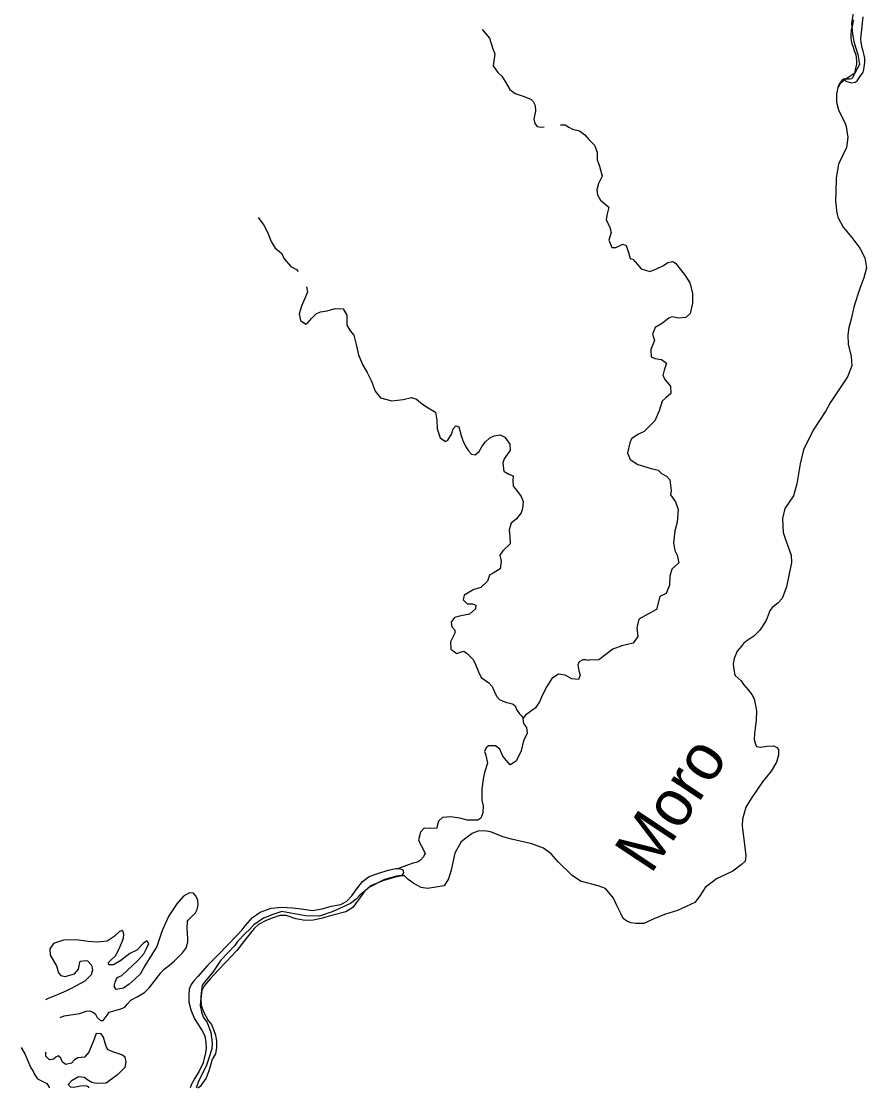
# Model space of a CAD drawing. Extents: x -492261 to -432772, y 1441225 to 1452922.
# Drawn here: x -459430.8 to -459334.4, y 1451554.7 to 1451676.4 of the extents above; entities that cross this region are included whole.
import ezdxf

# ---------------------------------------------------------------- set-up
doc = ezdxf.new("R2010")
doc.units = 0
doc.layers.add('Default', color=7, linetype='Continuous')

msp = doc.modelspace()

# ---------------------------------------------------------------- linework, layer by layer
at = {"layer": 'Default'}
for points in [[(-459335.93, 1451677.35), (-459336.12, 1451676.24), (-459336.01, 1451674.97), (-459335.8, 1451673.97), (-459335.38, 1451672.63), (-459335.2, 1451671.51), (-459335.74, 1451670.52), (-459336.4, 1451670.07), (-459336.92, 1451669.75), (-459337.45, 1451669.28), (-459337.66, 1451668.88), (-459337.81, 1451668.12), (-459337.81, 1451667.22), (-459337.58, 1451666.32), (-459337.29, 1451665.68), (-459336.87, 1451664.89), (-459336.7, 1451664.42), (-459336.51, 1451663.17), (-459336.68, 1451662.02), (-459337.59, 1451660.13), (-459337.87, 1451658.57), (-459337.89, 1451656.89), (-459337.93, 1451655.96), (-459337.86, 1451655.31), (-459337.8, 1451654.76), (-459337.65, 1451654.09), (-459337.04, 1451652.93), (-459336.06, 1451651.76), (-459335.17, 1451650.56), (-459334.58, 1451649.43), (-459334.38, 1451648.31), (-459334.69, 1451647.15), (-459335.15, 1451645.93), (-459335.79, 1451643.98), (-459336.16, 1451642.44), (-459336.41, 1451641.48), (-459336.53, 1451640.65), (-459336.47, 1451639.59), (-459336.16, 1451638.18), (-459336.07, 1451637.13), (-459336.58, 1451635.88), (-459337.49, 1451634.48), (-459338.54, 1451632.89), (-459339.03, 1451631.99), (-459340.46, 1451629.79), (-459341.57, 1451627.55), (-459341.97, 1451625.94), (-459342.34, 1451623.64), (-459342.73, 1451622.28), (-459343.73, 1451620.82), (-459343.99, 1451619.68), (-459343.92, 1451618.11), (-459343.7, 1451617.54), (-459343.32, 1451616.45), (-459342.99, 1451615.53), (-459342.94, 1451614.68), (-459343.52, 1451611.9), (-459344.01, 1451610.58), (-459344.51, 1451610.02), (-459345.17, 1451609.52), (-459345.41, 1451609.14)], [(-459335.87, 1451676.61), (-459335.95, 1451676.3), (-459336.04, 1451675.82), (-459336.13, 1451675.47), (-459336.2, 1451674.85), (-459336.2, 1451674.54), (-459336.14, 1451674.23), (-459336.06, 1451673.87), (-459335.97, 1451673.61), (-459335.79, 1451673.12), (-459335.61, 1451672.62), (-459335.57, 1451672.3), (-459335.54, 1451671.84), (-459335.55, 1451671.55), (-459335.69, 1451670.91), (-459335.78, 1451670.44), (-459335.9, 1451670.15), (-459335.97, 1451670.02), (-459336.09, 1451669.89), (-459336.29, 1451669.85), (-459336.56, 1451669.83), (-459336.85, 1451669.84), (-459337.02, 1451669.83), (-459336.92, 1451669.74), (-459336.78, 1451669.63), (-459336.62, 1451669.56), (-459336.39, 1451669.49), (-459336.14, 1451669.43), (-459335.9, 1451669.45), (-459335.68, 1451669.49), (-459335.46, 1451669.64), (-459335.3, 1451669.88), (-459335.15, 1451670.09), (-459334.79, 1451670.63), (-459334.71, 1451670.93), (-459334.58, 1451671.75), (-459334.59, 1451672.19), (-459334.66, 1451672.59), (-459334.77, 1451673.03), (-459334.9, 1451673.42), (-459335.02, 1451674.05), (-459335.05, 1451674.44), (-459335, 1451674.88), (-459334.93, 1451675.45), (-459334.85, 1451676.28), (-459334.77, 1451676.95)], [(-459378.23, 1451675.51), (-459377.4, 1451674.51), (-459377.08, 1451673.41), (-459376.78, 1451672.72)], [(-459376.78, 1451672.72), (-459376.98, 1451671.34), (-459376.47, 1451670.58), (-459376, 1451670.17), (-459375.61, 1451669.55), (-459375.1, 1451668.66), (-459374.46, 1451668.2), (-459373.55, 1451667.91), (-459372.68, 1451667.55), (-459372.41, 1451667.3), (-459372.2, 1451666.82), (-459372.17, 1451666.18), (-459372.33, 1451665.32), (-459372.22, 1451664.78), (-459371.97, 1451664.43), (-459371.56, 1451664.35), (-459371.18, 1451664.39)], [(-459337.02, 1451669.83), (-459337.22, 1451669.67), (-459337.35, 1451669.49), (-459337.5, 1451669.25), (-459337.66, 1451668.88), (-459337.81, 1451668.12), (-459337.81, 1451667.22), (-459337.58, 1451666.32), (-459337.29, 1451665.68), (-459336.87, 1451664.89), (-459336.7, 1451664.42), (-459336.51, 1451663.17), (-459336.68, 1451662.02), (-459337.59, 1451660.13), (-459337.87, 1451658.57), (-459337.89, 1451656.89), (-459337.93, 1451655.96), (-459337.86, 1451655.31), (-459337.8, 1451654.76), (-459337.65, 1451654.09), (-459337.04, 1451652.93), (-459336.06, 1451651.76), (-459335.17, 1451650.56), (-459334.58, 1451649.43), (-459334.38, 1451648.31), (-459334.69, 1451647.15), (-459335.15, 1451645.93), (-459335.79, 1451643.98), (-459336.16, 1451642.44), (-459336.41, 1451641.48), (-459336.53, 1451640.65), (-459336.47, 1451639.59), (-459336.16, 1451638.18), (-459336.07, 1451637.13), (-459336.58, 1451635.88), (-459337.49, 1451634.48), (-459338.54, 1451632.89), (-459339.03, 1451631.99), (-459340.46, 1451629.79), (-459341.57, 1451627.55), (-459341.97, 1451625.94), (-459342.34, 1451623.64), (-459342.73, 1451622.28), (-459343.73, 1451620.82), (-459343.99, 1451619.68), (-459343.92, 1451618.11), (-459343.7, 1451617.54), (-459343.32, 1451616.45), (-459342.99, 1451615.53), (-459342.94, 1451614.68), (-459343.52, 1451611.9), (-459344.01, 1451610.58), (-459344.51, 1451610.02), (-459345.17, 1451609.52), (-459345.41, 1451609.14)], [(-459369.32, 1451664.63), (-459368.76, 1451664.61), (-459368.35, 1451664.35), (-459367.94, 1451664.14), (-459367.13, 1451663.95), (-459366.53, 1451663.49), (-459366.05, 1451662.9), (-459365.44, 1451662.32), (-459365.14, 1451661.49), (-459365.12, 1451660.62), (-459364.87, 1451659.89), (-459364.54, 1451658.77), (-459364.97, 1451657.94), (-459365.17, 1451657.21), (-459365.1, 1451656.62), (-459364.75, 1451656.03), (-459363.81, 1451655.24), (-459363.97, 1451654.47), (-459364.1, 1451653.8), (-459363.68, 1451652.92), (-459363.52, 1451652.35), (-459363.78, 1451651.46), (-459363.45, 1451650.61), (-459363.01, 1451650.61), (-459362.2, 1451650.99), (-459361.81, 1451650.84), (-459361.56, 1451650.07), (-459361.34, 1451649.38), (-459361.05, 1451649.29), (-459360.53, 1451648.7), (-459360.09, 1451648.17), (-459359.11, 1451647.9), (-459358.37, 1451648.18), (-459357.55, 1451648.58), (-459357.05, 1451648.9), (-459356.49, 1451649.03), (-459356.19, 1451648.83), (-459355.63, 1451648.13), (-459355.1, 1451647.44), (-459354.54, 1451646.58), (-459354.24, 1451645.43), (-459354.23, 1451644.26), (-459354.5, 1451643.09), (-459354.99, 1451642.64), (-459355.8, 1451642.55), (-459356.55, 1451642.72), (-459356.93, 1451642.55), (-459357.68, 1451641.98), (-459358.5, 1451641.48), (-459358.82, 1451640.74), (-459358.57, 1451640.01), (-459358.99, 1451638.99), (-459358.96, 1451638.15), (-459358.56, 1451637.95), (-459357.78, 1451637.85), (-459357.2, 1451637.41), (-459357.49, 1451636.61), (-459357.64, 1451636), (-459357.37, 1451635.53), (-459356.74, 1451634.78), (-459356.73, 1451633.96), (-459357.29, 1451633.48), (-459357.7, 1451633.09), (-459358.04, 1451631.99), (-459358.53, 1451630.83), (-459359.76, 1451629.61), (-459360.48, 1451629.3), (-459361.22, 1451628.8), (-459361.38, 1451628.33), (-459361.67, 1451627.19), (-459361.35, 1451626.43), (-459360.5, 1451625.84), (-459358.95, 1451625.42), (-459358.18, 1451625.2), (-459357.77, 1451624.84), (-459357.21, 1451624.53), (-459356.82, 1451624.09), (-459356.69, 1451622.89), (-459356.77, 1451622.39), (-459356.17, 1451621.6), (-459355.87, 1451620.74), (-459356, 1451619.26), (-459356.25, 1451618.28), (-459356.42, 1451616.92)], [(-459403.79, 1451654.06), (-459403.16, 1451653.19), (-459402.91, 1451652.74), (-459402.64, 1451652.18), (-459402.31, 1451651.3), (-459401.86, 1451650.55), (-459401.19, 1451650.01), (-459400.8, 1451649.31), (-459400.07, 1451648.47), (-459399.42, 1451648.11), (-459399.24, 1451647.88)], [(-459398.3, 1451646.13), (-459398.17, 1451645.53), (-459398.85, 1451643.91), (-459399.11, 1451643.04), (-459398.96, 1451642.28), (-459398.37, 1451641.88), (-459398.19, 1451641.95), (-459397.66, 1451642.54), (-459397.19, 1451643.05), (-459396.67, 1451643.27), (-459395.93, 1451643.38), (-459395.02, 1451643.66), (-459394.11, 1451643.62), (-459393.7, 1451642.89), (-459393.67, 1451641.76), (-459393.29, 1451641.12), (-459392.89, 1451640.62), (-459392.61, 1451639.56), (-459392.34, 1451638.36), (-459391.89, 1451637.26), (-459391.35, 1451636.35), (-459390.85, 1451635.35), (-459390.45, 1451634.24), (-459389.86, 1451633.48), (-459388.53, 1451633.11), (-459387.26, 1451633.28), (-459386.3, 1451633.49), (-459385.74, 1451633.33), (-459385.04, 1451632.73), (-459384.39, 1451632.34), (-459383.56, 1451631.82), (-459383.42, 1451630.91), (-459383.36, 1451629.92), (-459383.03, 1451628.91), (-459382.41, 1451628.5), (-459382.15, 1451628.65), (-459381.76, 1451629.33), (-459381.56, 1451629.92), (-459381.26, 1451630.28), (-459380.89, 1451630.14), (-459380.64, 1451629.17), (-459380.44, 1451628.6), (-459380.09, 1451627.89), (-459379.8, 1451627.42), (-459379.45, 1451627.05), (-459379.06, 1451626.96), (-459378.57, 1451627.36), (-459378.23, 1451627.96), (-459377.88, 1451628.44), (-459377.37, 1451628.91), (-459376.88, 1451629.14), (-459376.2, 1451629.25), (-459375.65, 1451628.97), (-459375.09, 1451628.17), (-459375.04, 1451627.49), (-459375.46, 1451626.87), (-459375.72, 1451626.51), (-459375.9, 1451626.06), (-459375.78, 1451625.07), (-459375.65, 1451625.02), (-459375.21, 1451624.77), (-459374.72, 1451624.58), (-459374.76, 1451624.03), (-459374.71, 1451623.37), (-459374.33, 1451622.94), (-459373.8, 1451622.21), (-459373.58, 1451621.65), (-459373.63, 1451620.85), (-459373.81, 1451620.36), (-459374.31, 1451619.67), (-459374.94, 1451619.16), (-459375.17, 1451618.4), (-459375.07, 1451617.59), (-459375.05, 1451616.8), (-459375.9, 1451616.02), (-459376.24, 1451615.53), (-459376.07, 1451614.78), (-459376.19, 1451613.96), (-459376.98, 1451613.46), (-459377.4, 1451613.22), (-459377.63, 1451612.55), (-459378.38, 1451611.84), (-459379.19, 1451611.6), (-459380.28, 1451610.96), (-459380.41, 1451610.42), (-459379.94, 1451609.97), (-459379.34, 1451609.96), (-459378.96, 1451609.79)], [(-459356.42, 1451616.92), (-459356.26, 1451616.05), (-459356.01, 1451615.51), (-459355.82, 1451614.64), (-459356.61, 1451613.92), (-459356.82, 1451613.1), (-459356.87, 1451612.07), (-459357.25, 1451611.13), (-459357.99, 1451610.81), (-459358.36, 1451609.3), (-459359.28, 1451608.81), (-459360.37, 1451608.22), (-459360.6, 1451607.23), (-459360.49, 1451606.24), (-459361, 1451605.46), (-459362.29, 1451605.17), (-459363.32, 1451604.78), (-459363.99, 1451604.28), (-459364.94, 1451603.57), (-459366.11, 1451603.53), (-459366.11, 1451603.5), (-459366.41, 1451603.57), (-459366.75, 1451603.57), (-459367.16, 1451603.34), (-459367.34, 1451602.98), (-459367.2, 1451602.31), (-459367.06, 1451601.81), (-459367.26, 1451601.34), (-459368, 1451601.39), (-459368.77, 1451601.82), (-459369.55, 1451601.92), (-459370.31, 1451601.45), (-459370.85, 1451600.54), (-459371.35, 1451599.59), (-459371.69, 1451598.76), (-459372.17, 1451598.1), (-459372.73, 1451597.66), (-459373.28, 1451597.27), (-459373.6, 1451596.86), (-459373.51, 1451596.3), (-459373.17, 1451595.86), (-459373.11, 1451595.19), (-459373.51, 1451594.33), (-459373.81, 1451593.17), (-459374.38, 1451592), (-459375.06, 1451591.58), (-459375.87, 1451592.56), (-459376.23, 1451593.37), (-459376.71, 1451593.77), (-459377.53, 1451593.74), (-459377.8, 1451593.53), (-459377.96, 1451593.1), (-459377.81, 1451592.67), (-459377.65, 1451591.77), (-459377.98, 1451590.69), (-459378.14, 1451589.96), (-459378.29, 1451588.84), (-459378.28, 1451587.54), (-459378.13, 1451586.91), (-459378.17, 1451586.1), (-459378.4, 1451585.51), (-459378.74, 1451585.25), (-459379.94, 1451585.26), (-459380.79, 1451585.48), (-459381.84, 1451585.65), (-459382.76, 1451585.58), (-459383.22, 1451585.14), (-459383.33, 1451584.78), (-459383.42, 1451584.36), (-459384.13, 1451584.3), (-459384.87, 1451584.34), (-459385.26, 1451583.89), (-459385.51, 1451583.03), (-459385.33, 1451582.58), (-459385.01, 1451582.05), (-459384.76, 1451581.47), (-459384.83, 1451581.34), (-459384.94, 1451581.08), (-459385.29, 1451580.7), (-459385.63, 1451580.49), (-459386.12, 1451580.36), (-459386.77, 1451580.12), (-459387.28, 1451579.94), (-459387.58, 1451579.82), (-459387.73, 1451579.75)], [(-459345.41, 1451609.14), (-459345.62, 1451608.68), (-459345.85, 1451608.07), (-459346.57, 1451606.94), (-459347.24, 1451606.27), (-459348.17, 1451605.66), (-459348.44, 1451605.43), (-459348.66, 1451605.12), (-459349.16, 1451604.55), (-459349.49, 1451603.72), (-459349.59, 1451603.11), (-459349.58, 1451602.74), (-459349.46, 1451601.99), (-459349.38, 1451601.77), (-459348.71, 1451601.16), (-459348.42, 1451600.74), (-459347.9, 1451600.13), (-459347.46, 1451599.6), (-459347.2, 1451599.13), (-459347.05, 1451598.36), (-459346.95, 1451597.73), (-459346.97, 1451596.73), (-459347.09, 1451595.75), (-459347.17, 1451595.15), (-459347.22, 1451594.47), (-459347.11, 1451594.07), (-459346.95, 1451593.68), (-459346.5, 1451593.61), (-459345.78, 1451593.71), (-459345, 1451593.74), (-459344.9, 1451593.72), (-459344.62, 1451593.55), (-459344.44, 1451593.33), (-459344.42, 1451592.7), (-459344.65, 1451591.9), (-459345.26, 1451590.85), (-459346.25, 1451589.66), (-459347.54, 1451587.74), (-459348.16, 1451586.75), (-459348.54, 1451585.4), (-459348.59, 1451584.63), (-459348.46, 1451583.68), (-459348.3, 1451582.48), (-459348.16, 1451581.18), (-459348.24, 1451580.58), (-459348.7, 1451580.16), (-459349.63, 1451579.43), (-459351.5, 1451578.59), (-459352.79, 1451577.57), (-459353.39, 1451576.68), (-459353.98, 1451575.88), (-459355.95, 1451574.97), (-459357.44, 1451574.49), (-459358.74, 1451573.97), (-459359.8, 1451573.49), (-459360.3, 1451573.47), (-459360.7, 1451573.46), (-459361.3, 1451573.54), (-459361.73, 1451573.73), (-459362.14, 1451574.04), (-459362.41, 1451574.63), (-459362.89, 1451575.52), (-459363.26, 1451576.38), (-459364.17, 1451577.48), (-459365, 1451577.76), (-459367.04, 1451578.32), (-459367.96, 1451578.96), (-459369.56, 1451580.52), (-459370.36, 1451581.44), (-459371.23, 1451582.09), (-459372.59, 1451582.55), (-459374.91, 1451583.1), (-459375.89, 1451583.37), (-459376.4, 1451583.58), (-459377.28, 1451583.93), (-459377.98, 1451584.05), (-459378.73, 1451584.03), (-459379.4, 1451583.73), (-459380.1, 1451583.21), (-459380.64, 1451582.79), (-459381.37, 1451581.49), (-459381.55, 1451580.61), (-459381.79, 1451579.55), (-459382.08, 1451578.58), (-459382.56, 1451577.79), (-459384.47, 1451577.46), (-459385.22, 1451577.58), (-459386.03, 1451578.06), (-459386.7, 1451578.49), (-459387.11, 1451578.9), (-459387.54, 1451578.94), (-459388.01, 1451578.87), (-459389.37, 1451578.48), (-459391.11, 1451577.62), (-459392.21, 1451576.7), (-459392.6, 1451576.27), (-459393.25, 1451575.77), (-459395.35, 1451574.8), (-459396.8, 1451574.3), (-459398.4, 1451574.37), (-459400.08, 1451574.65)], [(-459345.41, 1451609.14), (-459345.62, 1451608.68), (-459345.85, 1451608.07), (-459346.57, 1451606.94), (-459347.24, 1451606.27), (-459348.17, 1451605.66), (-459348.44, 1451605.43), (-459348.66, 1451605.12), (-459349.16, 1451604.55), (-459349.49, 1451603.72), (-459349.59, 1451603.11), (-459349.58, 1451602.74), (-459349.46, 1451601.99), (-459349.38, 1451601.77), (-459348.71, 1451601.16), (-459348.42, 1451600.74), (-459347.9, 1451600.13), (-459347.46, 1451599.6), (-459347.2, 1451599.13), (-459347.05, 1451598.36), (-459346.95, 1451597.73), (-459346.97, 1451596.73), (-459347.09, 1451595.75), (-459347.17, 1451595.15), (-459347.22, 1451594.47), (-459347.11, 1451594.07), (-459346.95, 1451593.68), (-459346.5, 1451593.61), (-459345.78, 1451593.71), (-459345, 1451593.74), (-459344.9, 1451593.72), (-459344.62, 1451593.55), (-459344.44, 1451593.33), (-459344.42, 1451592.7), (-459344.65, 1451591.9), (-459345.26, 1451590.85), (-459346.25, 1451589.66), (-459347.54, 1451587.74), (-459348.16, 1451586.75), (-459348.54, 1451585.4), (-459348.59, 1451584.63), (-459348.46, 1451583.68), (-459348.3, 1451582.48), (-459348.16, 1451581.18), (-459348.24, 1451580.58), (-459348.7, 1451580.16), (-459349.63, 1451579.43), (-459351.5, 1451578.59), (-459352.79, 1451577.57), (-459353.39, 1451576.68), (-459353.98, 1451575.88), (-459355.95, 1451574.97), (-459357.44, 1451574.49), (-459358.74, 1451573.97), (-459359.8, 1451573.49), (-459360.3, 1451573.47), (-459360.7, 1451573.46), (-459361.3, 1451573.54), (-459361.73, 1451573.73), (-459362.14, 1451574.04), (-459362.41, 1451574.63), (-459362.89, 1451575.52), (-459363.26, 1451576.38), (-459364.17, 1451577.48), (-459365, 1451577.76), (-459367.04, 1451578.32), (-459367.96, 1451578.96), (-459369.56, 1451580.52), (-459370.36, 1451581.44), (-459371.23, 1451582.09), (-459372.59, 1451582.55), (-459374.91, 1451583.1), (-459375.89, 1451583.37), (-459376.4, 1451583.58), (-459377.28, 1451583.93), (-459377.98, 1451584.05), (-459378.73, 1451584.03), (-459379.4, 1451583.73), (-459380.1, 1451583.21), (-459380.64, 1451582.79), (-459381.37, 1451581.49), (-459381.55, 1451580.61), (-459381.79, 1451579.55), (-459382.08, 1451578.58), (-459382.56, 1451577.79), (-459384.47, 1451577.46), (-459385.22, 1451577.58), (-459386.03, 1451578.06), (-459386.7, 1451578.49), (-459387.11, 1451578.9), (-459387.45, 1451578.93)], [(-459378.96, 1451609.79), (-459379.02, 1451609.4), (-459379.67, 1451608.79), (-459380.84, 1451608.54), (-459381.41, 1451608.41), (-459381.79, 1451607.87), (-459381.69, 1451607.33), (-459381.37, 1451606.97), (-459381.38, 1451606.6), (-459381.84, 1451605.62), (-459381.82, 1451604.78), (-459381.13, 1451604.29), (-459380.61, 1451604.48), (-459380.35, 1451604.54), (-459379.95, 1451604.28), (-459379.29, 1451603.65), (-459379.07, 1451603.21), (-459378.68, 1451602.21), (-459378.34, 1451601.56), (-459377.48, 1451600.95), (-459377.11, 1451600.53), (-459376.83, 1451599.91), (-459376.59, 1451599.41), (-459376.21, 1451599.02), (-459375.93, 1451598.88), (-459375.46, 1451598.7), (-459375.09, 1451598.62), (-459374.7, 1451598.52), (-459374.46, 1451598.3), (-459374.31, 1451597.9), (-459373.99, 1451597.4), (-459373.79, 1451597.21), (-459373.55, 1451596.92)], [(-459406.22, 1451572.09), (-459405.66, 1451572.73), (-459405.24, 1451573.24), (-459404.44, 1451574.16), (-459403.57, 1451574.78), (-459402.33, 1451575.23), (-459401.11, 1451575.35), (-459399.89, 1451575.28), (-459398.89, 1451575.15), (-459397.61, 1451574.97), (-459396.51, 1451575.14), (-459395.47, 1451575.47), (-459394.38, 1451575.64), (-459393.68, 1451576.03), (-459393.12, 1451576.64), (-459392.54, 1451577.43), (-459391.9, 1451578.27), (-459391.14, 1451578.83), (-459390.15, 1451579.18), (-459388.98, 1451579.58), (-459388.09, 1451579.75), (-459387.69, 1451579.75), (-459387.28, 1451579.61), (-459387.2, 1451579.24), (-459387.45, 1451578.93), (-459388.27, 1451578.72), (-459389.46, 1451578.37), (-459390.97, 1451577.76), (-459391.63, 1451577.2), (-459392.39, 1451576.15), (-459392.99, 1451575.29), (-459393.78, 1451574.8), (-459395.28, 1451574.42), (-459396.62, 1451574.06), (-459397.51, 1451573.87), (-459398.44, 1451573.83), (-459399.49, 1451574.01), (-459400.6, 1451574.39), (-459401.32, 1451574.4), (-459402.19, 1451574.08), (-459402.88, 1451573.81), (-459403.75, 1451573.35), (-459404.26, 1451572.91), (-459405.31, 1451571.56), (-459406.24, 1451570.39)], [(-459411.77, 1451573.86), (-459410.93, 1451574.69), (-459410.75, 1451575.06), (-459410.65, 1451575.62), (-459410.7, 1451576.16), (-459410.94, 1451576.66), (-459411.19, 1451576.92), (-459411.62, 1451576.96), (-459412.32, 1451576.6), (-459413.08, 1451575.73), (-459414, 1451574.34), (-459414.7, 1451572.77), (-459414.86, 1451572.35), (-459415.36, 1451570.86), (-459415.94, 1451569.95), (-459416.74, 1451568.64), (-459417.28, 1451567.71), (-459417.85, 1451567.16), (-459418.52, 1451566.54), (-459419.16, 1451566.1), (-459420.01, 1451565.96), (-459420.21, 1451566.31), (-459420.1, 1451566.78), (-459419.87, 1451567.33), (-459419.36, 1451567.56), (-459418.73, 1451568.1), (-459418.18, 1451568.64), (-459417.56, 1451569.22), (-459416.86, 1451570), (-459416.49, 1451570.71), (-459416.28, 1451571.2), (-459416.52, 1451571.49), (-459416.93, 1451571.18), (-459417.66, 1451570.42), (-459418.43, 1451570.06), (-459419.45, 1451569.24), (-459420.3, 1451568.75), (-459420.84, 1451568.77), (-459420.86, 1451569.04), (-459420.56, 1451569.33), (-459420.09, 1451569.8), (-459419.89, 1451570.12), (-459419.58, 1451570.79), (-459419.35, 1451571.32), (-459419.15, 1451571.82), (-459419.11, 1451572.24), (-459419.2, 1451572.53), (-459419.29, 1451572.67), (-459419.63, 1451572.58), (-459420.24, 1451571.99), (-459421.04, 1451571.47), (-459422.16, 1451571.36), (-459423.19, 1451571.44), (-459424.56, 1451571.63), (-459425.99, 1451571.59), (-459427.15, 1451571.19), (-459427.55, 1451570.58), (-459427.54, 1451569.88), (-459426.79, 1451568.63), (-459426.59, 1451567.86), (-459426.3, 1451567.53), (-459425.83, 1451567.41), (-459424.77, 1451567.74), (-459424.28, 1451568.28), (-459424.17, 1451568.85), (-459424.12, 1451569.19), (-459423.43, 1451569.27), (-459423.28, 1451569.2), (-459422.82, 1451568.71), (-459422.69, 1451568.19), (-459422.84, 1451567.62), (-459423.56, 1451566.9), (-459425.05, 1451566.11), (-459425.66, 1451565.81), (-459426.6, 1451565.36), (-459427.77, 1451564.91), (-459428.05, 1451564.76)], [(-459400.08, 1451574.65), (-459401.11, 1451574.84), (-459402.13, 1451574.51), (-459403.19, 1451574.1), (-459404.29, 1451573.33), (-459404.8, 1451572.79), (-459405.23, 1451572.38), (-459406.15, 1451571.44), (-459406.46, 1451570.98)], [(-459426.39, 1451562.74), (-459425.92, 1451562.94), (-459424.15, 1451563.2), (-459423.41, 1451563.48), (-459423.02, 1451563.51), (-459422.6, 1451563.33), (-459422.37, 1451563.13), (-459422.16, 1451562.75), (-459421.8, 1451562.42), (-459421.47, 1451562.42), (-459421.04, 1451563.01), (-459420.81, 1451563.34), (-459419.48, 1451563.73), (-459419, 1451563.91), (-459418.76, 1451564.26), (-459418.33, 1451564.74), (-459417.61, 1451565.1), (-459416.75, 1451565.61), (-459416.18, 1451566.16), (-459414.92, 1451567.86), (-459414.52, 1451568.25), (-459413.93, 1451568.72), (-459413.34, 1451569.22), (-459412.43, 1451570.11), (-459411.97, 1451570.75), (-459411.81, 1451571.39), (-459411.82, 1451571.76), (-459411.91, 1451572.92), (-459411.86, 1451573.73)], [(-459411.86, 1451573.73), (-459411.77, 1451573.86)], [(-459406.22, 1451572.09), (-459408.32, 1451569.95), (-459409.57, 1451568.67), (-459410.68, 1451567.43), (-459411.12, 1451566.94), (-459411.45, 1451566.51), (-459411.66, 1451565.97), (-459411.71, 1451565.28), (-459411.71, 1451564.5), (-459411.5, 1451563.61), (-459411.06, 1451562.6), (-459410.65, 1451561.94), (-459410.17, 1451561.24), (-459409.88, 1451560.65), (-459409.78, 1451559.91), (-459409.73, 1451559.21), (-459409.86, 1451558.49), (-459409.96, 1451558.09)], [(-459406.46, 1451570.98), (-459408.04, 1451569.28), (-459408.97, 1451567.91), (-459409.97, 1451566.76), (-459410.17, 1451566.43), (-459410.32, 1451565.51), (-459410.4, 1451564.08), (-459410.23, 1451563.25), (-459410.03, 1451562.75), (-459409.61, 1451562.18), (-459409.21, 1451561.02), (-459409.04, 1451559.87), (-459409.09, 1451559.19), (-459409.44, 1451558.09), (-459409.75, 1451557.19), (-459410.55, 1451555.57), (-459410.88, 1451554.74)], [(-459406.24, 1451570.39), (-459407.44, 1451569.1), (-459408.32, 1451568.18), (-459409.22, 1451567.2), (-459409.91, 1451566.41), (-459410.24, 1451565.87), (-459410.35, 1451564.86), (-459410.32, 1451564.17), (-459410.04, 1451563.4), (-459409.5, 1451562.42), (-459409.14, 1451561.94), (-459408.88, 1451561.37), (-459408.65, 1451560.75), (-459408.57, 1451560.04), (-459408.57, 1451559.34), (-459408.68, 1451558.6), (-459409.01, 1451558.04)], [(-459423.11, 1451554.74), (-459423.12, 1451554.79), (-459423.42, 1451554.94), (-459424.06, 1451554.91), (-459424.82, 1451554.77), (-459425.18, 1451554.81), (-459425.46, 1451555.12), (-459425.01, 1451555.59), (-459424.28, 1451556.03), (-459423.61, 1451555.94), (-459423.25, 1451555.62), (-459422.78, 1451555.37), (-459422.28, 1451555.25), (-459421.15, 1451555.31), (-459419.97, 1451556.16), (-459419.82, 1451556.26), (-459419.33, 1451556.72), (-459418.96, 1451557.08), (-459418.85, 1451557.7), (-459418.98, 1451558.22), (-459419.35, 1451558.5), (-459420.39, 1451558.82), (-459420.91, 1451559.07), (-459421.12, 1451559.35), (-459421.26, 1451559.82), (-459421.46, 1451560.51), (-459421.73, 1451560.87), (-459422.27, 1451560.93), (-459422.52, 1451560.28), (-459422.78, 1451559.63), (-459423.13, 1451558.78), (-459423.6, 1451558.22), (-459424.36, 1451558.14), (-459424.75, 1451557.92), (-459425.1, 1451557.54), (-459425.74, 1451557.38), (-459426.11, 1451557.67), (-459426.3, 1451558.09), (-459426.6, 1451558.39), (-459426.88, 1451558.22), (-459427.16, 1451557.99), (-459427.62, 1451557.9), (-459428.02, 1451558.33), (-459428.01, 1451558.71), (-459427.97, 1451558.82)], [(-459430.82, 1451559.32), (-459430.41, 1451558.61), (-459429.73, 1451557), (-459429.45, 1451556.53), (-459429.34, 1451556.33), (-459428.98, 1451555.75), (-459427.91, 1451555.21), (-459427.66, 1451554.79), (-459427.66, 1451554.74)], [(-459409.96, 1451558.09), (-459410.07, 1451557.59), (-459410.53, 1451556.63), (-459411.06, 1451555.76), (-459411.42, 1451555.15), (-459411.55, 1451554.74)], [(-459410.67, 1451554.74), (-459410.31, 1451555), (-459409.73, 1451555.79), (-459409.4, 1451556.7), (-459409.15, 1451557.48), (-459409.01, 1451558.04)]]:
    msp.add_lwpolyline(points, dxfattribs=at)

# ---------------------------------------------------------------- texts
msp.add_text('Moro', height=5.28, rotation=56.4381, dxfattribs=at).set_placement((-459359, 1451579))

doc.saveas('drawing.dxf')
